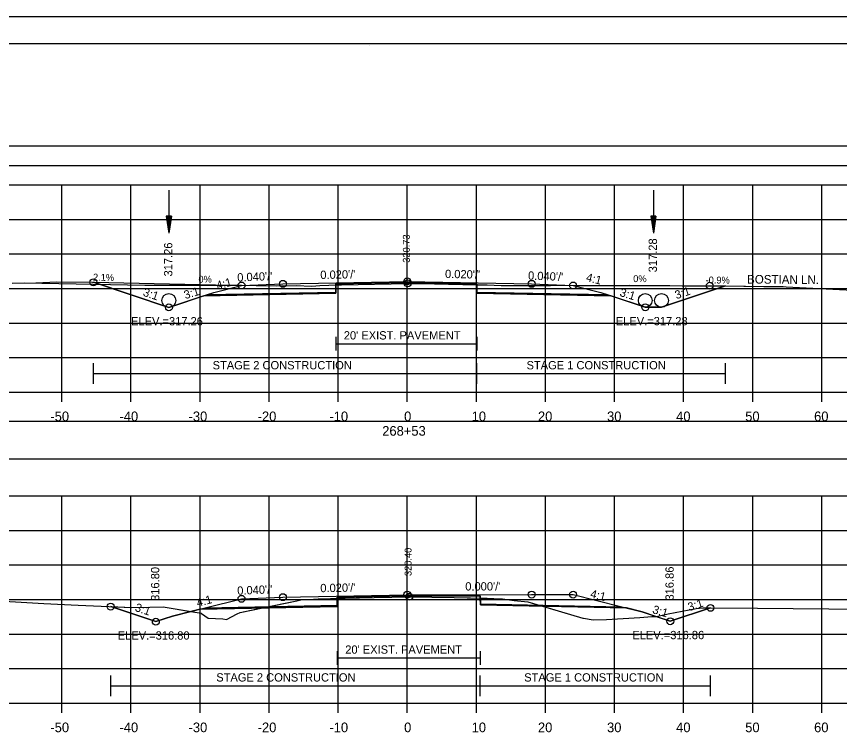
# Model space of a CAD drawing. Extents: x 1376273 to 1384221, y 378927 to 384592.
# Drawn here: x 1380135.1 to 1380254.2, y 383208.3 to 383311.9 of the extents above; entities that cross this region are included whole.
import ezdxf

# ---------------------------------------------------------------- set-up
doc = ezdxf.new("R2010")
doc.units = 0
for name, color, linetype in [('R_Alt Surface', 7, 'Continuous'), ('R_Alt Surface Annot', 7, 'Continuous'), ('R_Axis', 7, 'Continuous'), ('R_Axis Annot', 7, 'Continuous'), ('R_Border', 7, 'Continuous'), ('R_Border Notes', 7, 'Continuous'), ('R_Contours', 7, 'Continuous'), ('R_Dimension', 7, 'Continuous'), ('R_Drive', 7, 'Continuous'), ('R_Exist Surface', 7, 'Continuous'), ('R_Fin Surface', 7, 'Continuous'), ('R_Grid', 7, 'Continuous'), ('R_No Plot', 7, 'Continuous'), ('R_Water', 7, 'Continuous'), ('R_Xsect Elev', 7, 'Continuous'), ('R_Xsect Slope', 7, 'Continuous'), ('T_Detection Zones', 7, 'Continuous')]:
    doc.layers.add(name, color=color, linetype=linetype)

msp = doc.modelspace()

# ---------------------------------------------------------------- linework, layer by layer
at = {"layer": 'R_Alt Surface'}
for points in [[(1380162.72, 383271.66), (1380181.31, 383272.04), (1380181.32, 383273.2), (1380191.66, 383273.41), (1380201.72, 383273.21), (1380201.73, 383272.04), (1380220.59, 383271.66)], [(1380181.32, 383265.56), (1380181.32, 383263.56)], [(1380201.72, 383265.56), (1380201.72, 383263.56)], [(1380181.32, 383264.56), (1380201.72, 383264.56)], [(1380162.38, 383226.33), (1380181.52, 383226.71), (1380181.53, 383227.88), (1380191.66, 383228.08), (1380202.23, 383228.09), (1380202.24, 383226.92), (1380222.65, 383226.51)], [(1380181.53, 383220.1), (1380181.53, 383218.1)], [(1380181.53, 383219.1), (1380202.23, 383219.1)], [(1380202.23, 383220.1), (1380202.23, 383218.1)]]:
    msp.add_lwpolyline(points, dxfattribs=at)
at = {"layer": 'R_Alt Surface Annot'}
for centre in [(1380157.15, 383270.81), (1380226.1, 383270.83), (1380228.45, 383270.83)]:
    msp.add_circle(centre, 1, dxfattribs=at)
at = {"layer": 'R_Axis'}
for p, q in [((1380041.66, 383257.55), (1380341.66, 383257.55)), ((1380141.66, 383256.15), (1380141.66, 383257.55)), ((1380151.66, 383256.15), (1380151.66, 383257.55)), ((1380161.66, 383256.15), (1380161.66, 383257.55)), ((1380171.66, 383256.15), (1380171.66, 383257.55)), ((1380181.66, 383256.15), (1380181.66, 383257.55)), ((1380191.66, 383256.15), (1380191.66, 383257.55)), ((1380201.66, 383256.15), (1380201.66, 383257.55)), ((1380211.66, 383256.15), (1380211.66, 383257.55)), ((1380221.66, 383256.15), (1380221.66, 383257.55)), ((1380231.66, 383256.15), (1380231.66, 383257.55)), ((1380241.66, 383256.15), (1380241.66, 383257.55)), ((1380251.66, 383256.15), (1380251.66, 383257.55)), ((1380041.66, 383212.55), (1380341.66, 383212.55)), ((1380141.66, 383211.15), (1380141.66, 383212.55)), ((1380151.66, 383211.15), (1380151.66, 383212.55)), ((1380161.66, 383211.15), (1380161.66, 383212.55)), ((1380171.66, 383211.15), (1380171.66, 383212.55)), ((1380181.66, 383211.15), (1380181.66, 383212.55)), ((1380191.66, 383211.15), (1380191.66, 383212.55)), ((1380201.66, 383211.15), (1380201.66, 383212.55)), ((1380211.66, 383211.15), (1380211.66, 383212.55)), ((1380221.66, 383211.15), (1380221.66, 383212.55)), ((1380231.66, 383211.15), (1380231.66, 383212.55)), ((1380241.66, 383211.15), (1380241.66, 383212.55)), ((1380251.66, 383211.15), (1380251.66, 383212.55))]:
    msp.add_line(p, q, dxfattribs=at)
at = {"layer": 'R_Axis Annot'}
for points in [[(1380040.77, 383290.34), (1380342.57, 383290.34), (1380342.57, 383293.15), (1380040.77, 383293.15)], [(1380040.81, 383247.88), (1380342.5, 383247.88), (1380342.5, 383253.29), (1380040.81, 383253.29)]]:
    msp.add_lwpolyline(points, close=True, dxfattribs=at)
at = {"layer": 'R_Border'}
for p, q in [((1380033.66, 383308.01), (1380349.84, 383308.01)), ((1380186.18, 383307.75), (1380186.18, 383307.75)), ((1380186.18, 383307.75), (1380186.18, 383307.75))]:
    msp.add_line(p, q, dxfattribs=at)
at = {"layer": 'R_Contours'}
for points in [[(1380201.72, 383273.1), (1380202.72, 383273.08), (1380203.21, 383273.07), (1380205.24, 383273), (1380210.29, 383272.96), (1380212.41, 383273), (1380223.82, 383273.01), (1380231.44, 383272.95), (1380233.69, 383272.95), (1380237.42, 383272.94), (1380237.72, 383272.94), (1380237.72, 383272.92), (1380228.45, 383269.83), (1380226.1, 383269.83), (1380221.12, 383271.49), (1380201.73, 383271.87)], [(1380202.23, 383227.75), (1380203.23, 383227.73), (1380204.19, 383227.68), (1380205.42, 383227.63), (1380207.13, 383227.4), (1380209.12, 383227.19), (1380211.21, 383226.58), (1380202.24, 383226.76)], [(1380211.21, 383226.58), (1380217.07, 383224.86), (1380217.13, 383224.84), (1380217.14, 383224.84), (1380218.54, 383224.59), (1380220.48, 383224.67), (1380225.3, 383224.96), (1380227.07, 383225.08), (1380227.61, 383225.11), (1380225.66, 383225.76), (1380223.37, 383226.33)], [(1380227.61, 383225.11), (1380227.93, 383225.13), (1380229.44, 383225.47), (1380233.46, 383226.25), (1380234.45, 383226.35), (1380235.54, 383226.34), (1380229.72, 383224.41)]]:
    msp.add_lwpolyline(points, close=True, dxfattribs=at)
at = {"layer": 'R_Dimension'}
for p, q in [((1380146.23, 383258.75), (1380146.23, 383261.75)), ((1380201.72, 383258.75), (1380201.72, 383261.75)), ((1380237.72, 383258.75), (1380237.72, 383261.75)), ((1380146.23, 383260.25), (1380237.72, 383260.25)), ((1380148.73, 383213.58), (1380148.73, 383216.58)), ((1380202.23, 383213.58), (1380202.23, 383216.58)), ((1380235.54, 383213.58), (1380235.54, 383216.58)), ((1380148.73, 383215.08), (1380235.54, 383215.08))]:
    msp.add_line(p, q, dxfattribs=at)
at = {"layer": 'R_Drive'}
for p, q in [((1380153.66, 383272.98), (1380136.25, 383273.34)), ((1380167.66, 383272.98), (1380153.66, 383272.98)), ((1380215.66, 383272.98), (1380229.66, 383272.98)), ((1380229.66, 383272.98), (1380246.05, 383272.83))]:
    msp.add_line(p, q, dxfattribs=at)
at = {"layer": 'R_Exist Surface'}
for points in [[(1380134.48, 383273.3), (1380137.89, 383273.37), (1380140.91, 383273.49), (1380146.1, 383273.45), (1380148.47, 383273.41), (1380155, 383273.27), (1380163.9, 383273.1), (1380172.72, 383272.94), (1380175.58, 383272.96), (1380177.82, 383272.89), (1380179.02, 383272.97), (1380180.32, 383273.05), (1380182.13, 383273.09), (1380191.72, 383273.28), (1380193.54, 383273.25), (1380202.72, 383273.08), (1380203.21, 383273.07), (1380205.24, 383273), (1380210.29, 383272.96), (1380212.41, 383273), (1380223.82, 383273.01), (1380231.44, 383272.95), (1380233.69, 383272.95), (1380237.42, 383272.94), (1380243.28, 383272.86), (1380245.54, 383272.86), (1380258.1, 383272.22)], [(1380129.16, 383227.56), (1380139.04, 383226.95), (1380144.02, 383226.71), (1380151.79, 383226.41), (1380154.37, 383226.42), (1380156.32, 383226.49), (1380161.8, 383225.56), (1380161.84, 383225.56), (1380161.85, 383225.55), (1380162.85, 383224.85), (1380164.98, 383224.74), (1380165.5, 383224.68), (1380167.05, 383225.47), (1380167.47, 383225.67), (1380175.68, 383227.36), (1380176.44, 383227.54), (1380176.64, 383227.55), (1380178.07, 383227.62), (1380178.77, 383227.64), (1380180.53, 383227.71), (1380186.85, 383227.84), (1380191.97, 383227.95), (1380198.42, 383227.82), (1380203.23, 383227.73), (1380204.19, 383227.68), (1380205.42, 383227.63), (1380207.13, 383227.4), (1380209.12, 383227.19), (1380217.07, 383224.86), (1380217.13, 383224.84), (1380217.14, 383224.84), (1380218.54, 383224.59), (1380220.48, 383224.67), (1380225.3, 383224.96), (1380227.07, 383225.08), (1380227.93, 383225.13), (1380229.44, 383225.47), (1380233.46, 383226.25), (1380234.45, 383226.35), (1380242.35, 383226.32), (1380252.69, 383226.22), (1380257.17, 383226.17)]]:
    msp.add_lwpolyline(points, dxfattribs=at)
at = {"layer": 'R_Fin Surface'}
for points in [[(1380146.23, 383273.45), (1380157.15, 383269.81), (1380162.74, 383271.67), (1380163.66, 383271.98), (1380167.66, 383272.98), (1380173.66, 383273.22), (1380191.66, 383273.58), (1380209.66, 383273.22), (1380215.66, 383272.98), (1380219.66, 383271.98), (1380220.57, 383271.67), (1380226.1, 383269.83), (1380228.45, 383269.83), (1380237.72, 383272.92)], [(1380148.73, 383226.53), (1380155.26, 383224.35), (1380157.66, 383225.15), (1380162.41, 383226.34), (1380167.66, 383227.65), (1380173.66, 383227.89), (1380191.66, 383228.25), (1380209.66, 383228.26), (1380215.66, 383228.26), (1380222.53, 383226.54), (1380225.66, 383225.76), (1380229.72, 383224.41), (1380235.54, 383226.34)]]:
    msp.add_lwpolyline(points, dxfattribs=at)
at = {"layer": 'R_Grid'}
for p, q in [((1380041.66, 383287.55), (1380341.66, 383287.55)), ((1380141.66, 383257.55), (1380141.66, 383287.55)), ((1380151.66, 383257.55), (1380151.66, 383287.55)), ((1380161.66, 383257.55), (1380161.66, 383287.55)), ((1380171.66, 383257.55), (1380171.66, 383287.55)), ((1380181.66, 383257.55), (1380181.66, 383287.55)), ((1380191.66, 383257.55), (1380191.66, 383287.55)), ((1380201.66, 383257.55), (1380201.66, 383287.55)), ((1380211.66, 383257.55), (1380211.66, 383287.55)), ((1380221.66, 383257.55), (1380221.66, 383287.55)), ((1380231.66, 383257.55), (1380231.66, 383287.55)), ((1380241.66, 383257.55), (1380241.66, 383287.55)), ((1380251.66, 383257.55), (1380251.66, 383287.55)), ((1380041.66, 383282.55), (1380341.66, 383282.55)), ((1380041.66, 383277.55), (1380341.66, 383277.55)), ((1380041.66, 383272.55), (1380341.66, 383272.55)), ((1380041.66, 383267.55), (1380341.66, 383267.55)), ((1380041.66, 383262.55), (1380341.66, 383262.55)), ((1380041.66, 383257.55), (1380341.66, 383257.55)), ((1380041.66, 383242.55), (1380341.66, 383242.55)), ((1380141.66, 383212.55), (1380141.66, 383242.55)), ((1380151.66, 383212.55), (1380151.66, 383242.55)), ((1380161.66, 383212.55), (1380161.66, 383242.55)), ((1380171.66, 383212.55), (1380171.66, 383242.55)), ((1380181.66, 383212.55), (1380181.66, 383242.55)), ((1380191.66, 383212.55), (1380191.66, 383242.55)), ((1380201.66, 383212.55), (1380201.66, 383242.55)), ((1380211.66, 383212.55), (1380211.66, 383242.55)), ((1380221.66, 383212.55), (1380221.66, 383242.55)), ((1380231.66, 383212.55), (1380231.66, 383242.55)), ((1380241.66, 383212.55), (1380241.66, 383242.55)), ((1380251.66, 383212.55), (1380251.66, 383242.55)), ((1380041.66, 383237.55), (1380341.66, 383237.55)), ((1380041.66, 383232.55), (1380341.66, 383232.55)), ((1380041.66, 383227.55), (1380341.66, 383227.55)), ((1380041.66, 383222.55), (1380341.66, 383222.55)), ((1380041.66, 383217.55), (1380341.66, 383217.55)), ((1380041.66, 383212.55), (1380341.66, 383212.55))]:
    msp.add_line(p, q, dxfattribs=at)
at = {"layer": 'R_No Plot'}
msp.add_line((1380021.26, 383311.9), (1380354.59, 383311.9), dxfattribs=at)
for points in [[(1380021.25, 383311.9), (1380354.59, 383311.9), (1380354.59, 383098.57), (1380021.25, 383098.57)], [(1380267.58, 383308.01), (1380267.58, 383298.13), (1380303.31, 383298.13), (1380303.31, 383295.21), (1380326.51, 383295.21), (1380326.51, 383270.88), (1380349.84, 383270.88), (1380349.84, 383102.55), (1380033.66, 383102.55), (1380033.66, 383308.01)]]:
    msp.add_lwpolyline(points, close=True, dxfattribs=at)
for points in [[(1380162.19, 383271.49), (1380181.31, 383271.87), (1380181.32, 383273.2), (1380191.66, 383273.41), (1380201.72, 383273.21), (1380201.73, 383271.87), (1380221.12, 383271.49)], [(1380161.66, 383226.15), (1380181.52, 383226.55), (1380181.53, 383227.88), (1380191.66, 383228.08), (1380202.23, 383228.09), (1380202.24, 383226.76), (1380223.37, 383226.33)]]:
    msp.add_lwpolyline(points, dxfattribs=at)
for centre in [(1380146.23, 383273.45), (1380191.66, 383273.58), (1380167.66, 383272.98), (1380173.66, 383273.22), (1380191.72, 383273.28), (1380209.66, 383273.22), (1380215.66, 383272.98), (1380235.44, 383272.94), (1380157.15, 383269.81), (1380157.15, 383269.81), (1380226.1, 383269.83), (1380226.1, 383269.83), (1380226.1, 383269.83), (1380191.66, 383228.25), (1380209.66, 383228.26), (1380215.66, 383228.26), (1380167.66, 383227.65), (1380173.66, 383227.89), (1380191.97, 383227.95), (1380148.73, 383226.53), (1380235.54, 383226.34), (1380155.26, 383224.35), (1380155.26, 383224.35), (1380229.72, 383224.41), (1380229.72, 383224.41)]:
    msp.add_circle(centre, 0.5, dxfattribs=at)
at = {"layer": 'R_Water'}
for p, q in [((1380157.15, 383286.78), (1380157.15, 383280.53)), ((1380227.28, 383286.78), (1380227.28, 383280.53)), ((1380156.78, 383283.03), (1380157.15, 383280.53)), ((1380157.53, 383283.03), (1380156.78, 383283.03)), ((1380156.84, 383283.03), (1380157.15, 383280.95)), ((1380156.9, 383283.03), (1380157.15, 383281.38)), ((1380156.96, 383283.03), (1380157.15, 383281.8)), ((1380157.03, 383283.03), (1380157.15, 383282.22)), ((1380157.09, 383283.03), (1380157.15, 383282.64)), ((1380157.53, 383283.03), (1380157.15, 383280.53)), ((1380157.27, 383283.03), (1380157.15, 383282.22)), ((1380157.4, 383283.03), (1380157.15, 383281.38)), ((1380157.46, 383283.03), (1380157.15, 383280.95)), ((1380157.34, 383283.03), (1380157.15, 383281.8)), ((1380157.21, 383283.03), (1380157.15, 383282.64)), ((1380226.9, 383283.03), (1380227.28, 383280.53)), ((1380227.65, 383283.03), (1380226.9, 383283.03)), ((1380226.96, 383283.03), (1380227.28, 383280.95)), ((1380227.03, 383283.03), (1380227.28, 383281.38)), ((1380227.09, 383283.03), (1380227.28, 383281.8)), ((1380227.15, 383283.03), (1380227.28, 383282.22)), ((1380227.22, 383283.03), (1380227.28, 383282.64)), ((1380227.65, 383283.03), (1380227.28, 383280.53)), ((1380227.4, 383283.03), (1380227.28, 383282.22)), ((1380227.52, 383283.03), (1380227.28, 383281.38)), ((1380227.59, 383283.03), (1380227.28, 383280.95)), ((1380227.46, 383283.03), (1380227.28, 383281.8)), ((1380227.33, 383283.03), (1380227.28, 383282.64))]:
    msp.add_line(p, q, dxfattribs=at)
at = {"layer": 'T_Detection Zones'}
for points in [[(1380146.23, 383273.45), (1380148.47, 383273.41), (1380155, 383273.27), (1380163.9, 383273.1), (1380172.72, 383272.94), (1380175.58, 383272.96), (1380177.82, 383272.89), (1380179.02, 383272.97), (1380180.32, 383273.05), (1380181.32, 383273.07), (1380181.31, 383271.87), (1380162.19, 383271.49), (1380157.15, 383269.81)], [(1380181.32, 383273.07), (1380182.13, 383273.09), (1380191.72, 383273.28), (1380193.54, 383273.25), (1380201.72, 383273.1), (1380201.72, 383273.21), (1380191.66, 383273.41), (1380181.32, 383273.2)], [(1380170.67, 383226.33), (1380175.68, 383227.36), (1380176.44, 383227.54), (1380176.64, 383227.55), (1380178.07, 383227.62), (1380178.77, 383227.64), (1380180.53, 383227.71), (1380181.53, 383227.73), (1380181.52, 383226.55)], [(1380181.53, 383227.73), (1380186.85, 383227.84), (1380191.97, 383227.95), (1380198.42, 383227.82), (1380202.23, 383227.75), (1380202.23, 383228.09), (1380191.66, 383228.08), (1380181.53, 383227.88)], [(1380148.73, 383226.53), (1380151.79, 383226.41), (1380154.37, 383226.42), (1380156.32, 383226.49), (1380160.32, 383225.82), (1380157.66, 383225.15), (1380155.26, 383224.35)], [(1380160.32, 383225.82), (1380161.8, 383225.56), (1380161.84, 383225.56), (1380161.85, 383225.55), (1380162.85, 383224.85), (1380164.98, 383224.74), (1380165.5, 383224.68), (1380167.05, 383225.47), (1380167.47, 383225.67), (1380170.67, 383226.33), (1380161.66, 383226.15)]]:
    msp.add_lwpolyline(points, close=True, dxfattribs=at)

# ---------------------------------------------------------------- texts
at = {"layer": 'R_Alt Surface'}
for p in [(1380182.47, 383265.17), (1380182.68, 383219.71)]:
    msp.add_text("20' EXIST. PAVEMENT", height=1.2, dxfattribs=at).set_placement(p)
at = {"layer": 'R_Axis Annot'}
for s, p in [('-50', (1380140, 383253.35)), ('-40', (1380150, 383253.35)), ('-30', (1380160, 383253.35)), ('-20', (1380170, 383253.35)), ('-10', (1380180.39, 383253.35)), ('0', (1380191.2, 383253.35)), ('10', (1380200.97, 383253.35)), ('20', (1380210.57, 383253.35)), ('30', (1380220.57, 383253.35)), ('40', (1380230.57, 383253.35)), ('50', (1380240.57, 383253.35)), ('60', (1380250.54, 383253.35)), ('268+53', (1380188.03, 383251.25)), ('-50', (1380140, 383208.35)), ('-40', (1380150, 383208.35)), ('-30', (1380160, 383208.35)), ('-20', (1380170, 383208.35)), ('-10', (1380180.39, 383208.35)), ('0', (1380191.2, 383208.35)), ('10', (1380200.97, 383208.35)), ('20', (1380210.57, 383208.35)), ('30', (1380220.57, 383208.35)), ('40', (1380230.57, 383208.35)), ('50', (1380240.57, 383208.35)), ('60', (1380250.54, 383208.35))]:
    msp.add_text(s, height=1.4, dxfattribs=at).set_placement(p)
at = {"layer": 'R_Border Notes'}
for s, p in [('ELEV.=317.26', (1380151.68, 383267.21)), ('ELEV.=317.28', (1380221.84, 383267.23)), ('ELEV.=316.80', (1380149.75, 383221.75)), ('ELEV.=316.86', (1380224.23, 383221.81))]:
    msp.add_text(s, height=1.2, dxfattribs=at).set_placement(p)
at = {"layer": 'R_Dimension'}
for s, p in [('STAGE 2 CONSTRUCTION', (1380163.48, 383260.85)), ('STAGE 1 CONSTRUCTION', (1380208.92, 383260.85)), ('STAGE 2 CONSTRUCTION', (1380164.01, 383215.68)), ('STAGE 1 CONSTRUCTION', (1380208.58, 383215.68))]:
    msp.add_text(s, height=1.2, dxfattribs=at).set_placement(p)
at = {"layer": 'R_Drive'}
for s, height, rotation, p in [('2.1%', 1, 358.8158, (1380146.16, 383273.69)), ('-0.9%', 1, 359.5079, (1380234.83, 383273.28)), ('BOSTIAN LN.', 1.25, 359.5079, (1380240.84, 383273.27))]:
    msp.add_text(s, height=height, rotation=rotation, dxfattribs=at).set_placement(p)
for p in [(1380161.43, 383273.38), (1380224.36, 383273.47)]:
    msp.add_text('0%', height=1, dxfattribs=at).set_placement(p)
at = {"layer": 'R_Xsect Elev'}
for s, height, p in [('320.73', 1, (1380192.02, 383276.28)), ('317.26', 1.2, (1380157.65, 383274.29)), ('317.28', 1.2, (1380227.79, 383274.89)), ('320.40', 1, (1380192.27, 383230.95)), ('316.80', 1.2, (1380155.76, 383227.35)), ('316.86', 1.2, (1380230.22, 383227.41))]:
    msp.add_text(s, height=height, rotation=90, dxfattribs=at).set_placement(p)
at = {"layer": 'R_Xsect Slope'}
for s, rotation, p in [("0.040'/'", 2.2906, (1380167.07, 383273.55)), ("0.020'/'", 1.1458, (1380179.08, 383273.92)), ("0.020'/'", 358.8542, (1380197.11, 383274.07)), ("0.040'/'", 357.7094, (1380209.12, 383273.84)), ('4:1', 15.5158, (1380164.21, 383272.38)), ('4:1', 345.9638, (1380217.45, 383273.64)), ('3:1', 16.7836, (1380159.53, 383271)), ('3:1', 18.4349, (1380230.61, 383270.99)), ('3:1', 341.5651, (1380153.31, 383271.52)), ('3:1', 343.2269, (1380222.32, 383271.48)), ("0.020'/'", 1.1458, (1380179.08, 383228.6)), ("0.000'/'", 0.0257, (1380200.05, 383228.85)), ("0.040'/'", 2.2906, (1380167.07, 383228.23)), ('4:1', 345.9638, (1380218.06, 383227.85)), ('4:1', 14.9015, (1380161.33, 383226.48)), ('3:1', 18.4349, (1380232.48, 383225.85)), ('3:1', 341.5651, (1380152.15, 383225.92)), ('3:1', 343.2269, (1380227.05, 383225.6))]:
    msp.add_text(s, height=1.2, rotation=rotation, dxfattribs=at).set_placement(p)

doc.saveas('drawing.dxf')
